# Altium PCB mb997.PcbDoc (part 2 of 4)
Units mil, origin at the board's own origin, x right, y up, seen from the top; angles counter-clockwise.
Board outline 2598.43 x 3818.9 mil, 2 copper layers (Top, Bottom), stack 62.402 mil thick; 205 components, 190 nets, 761 pads, 492 vias.
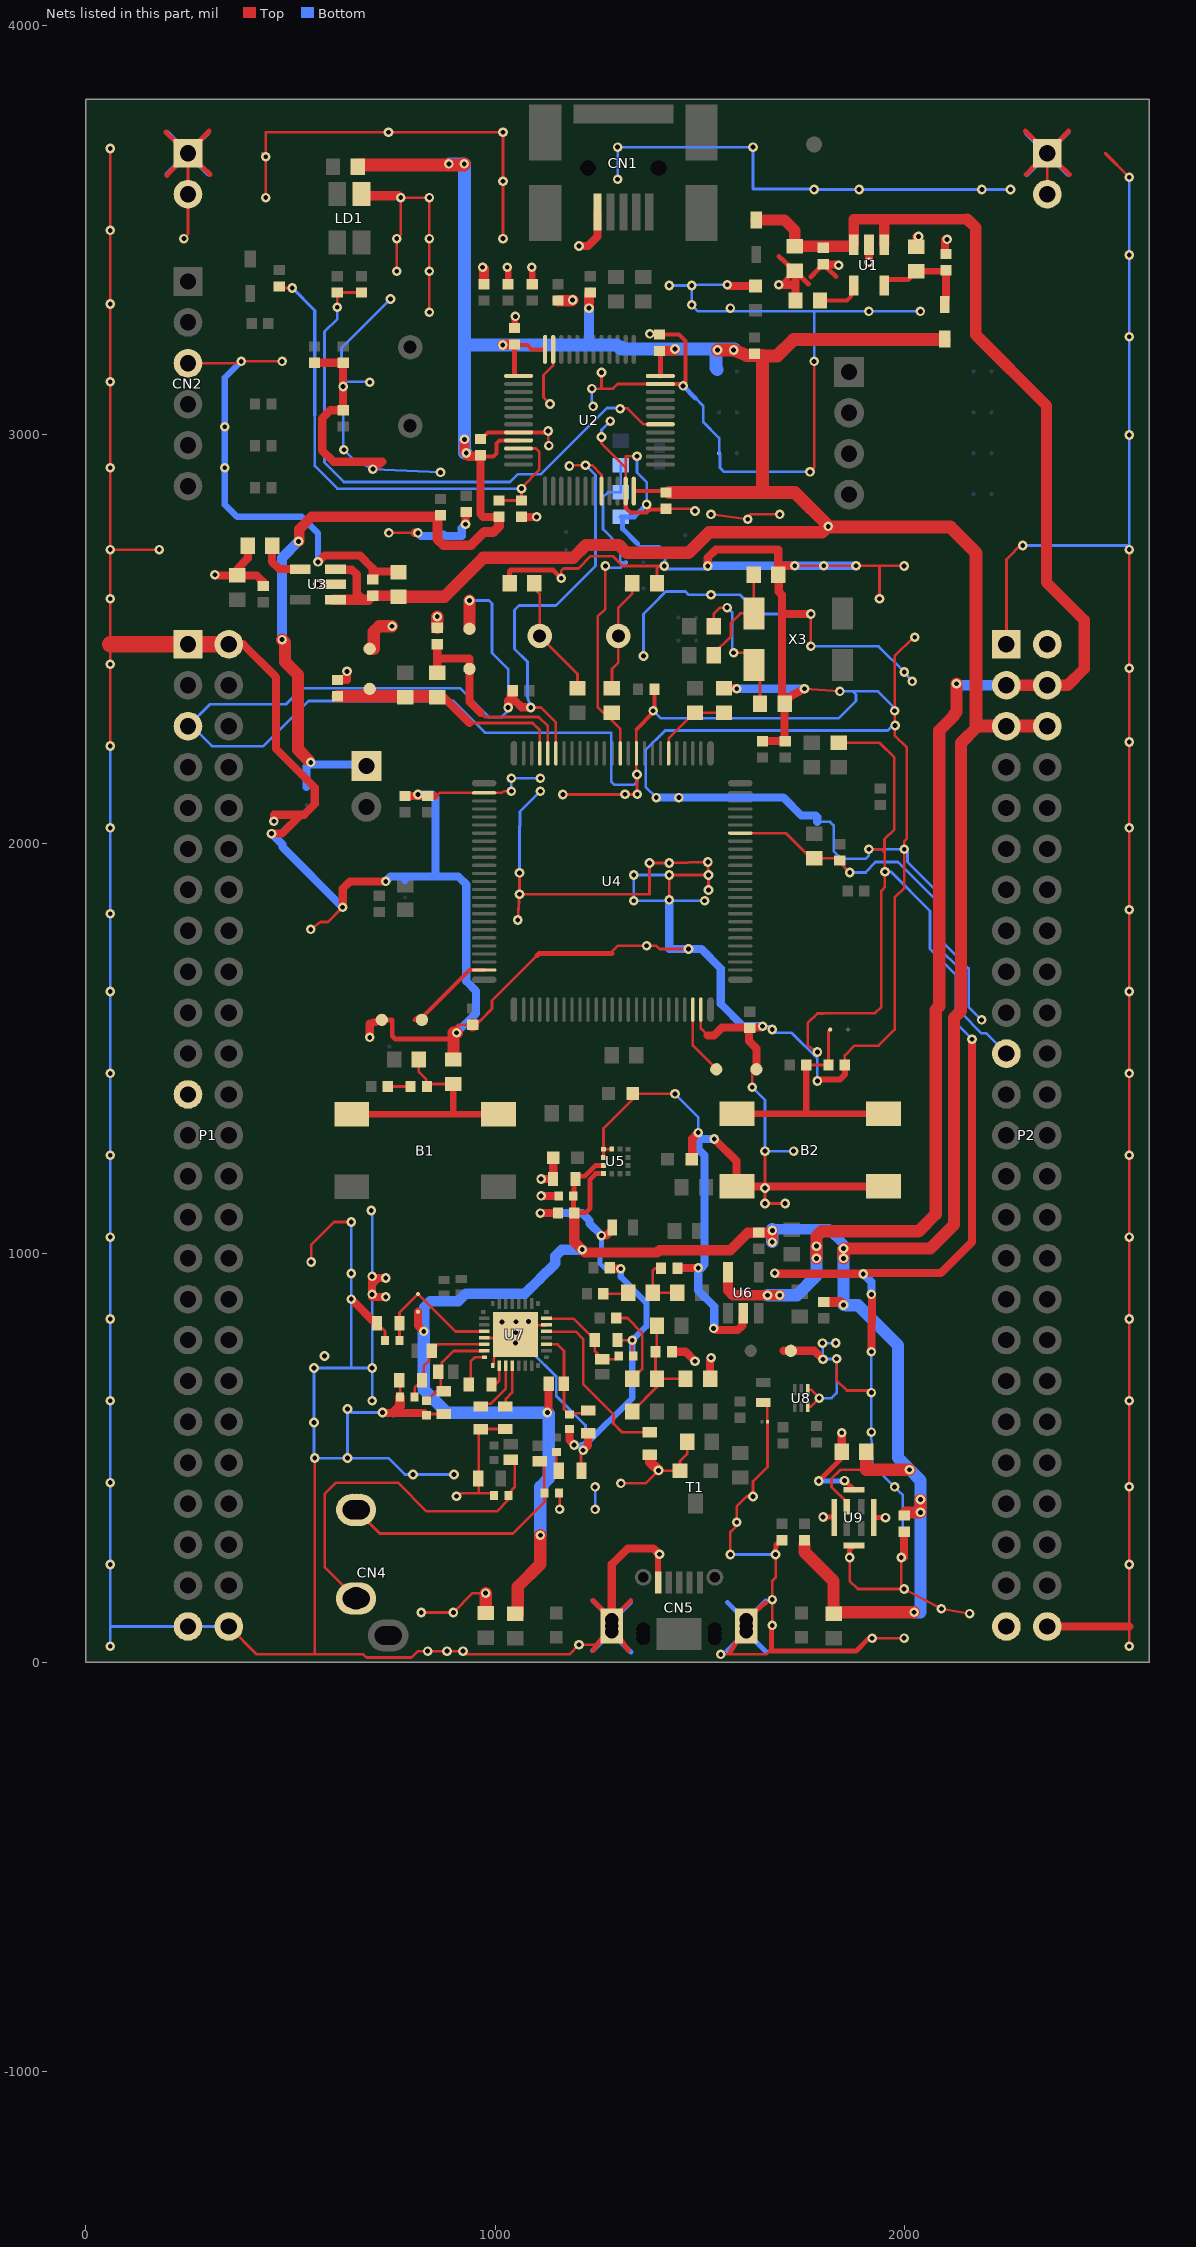
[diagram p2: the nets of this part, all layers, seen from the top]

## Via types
v1: diameter 23.62, hole 11.81, Top to Bottom, 485 vias
v2: diameter 19.68, hole 11.81, Top to Bottom, 7 vias

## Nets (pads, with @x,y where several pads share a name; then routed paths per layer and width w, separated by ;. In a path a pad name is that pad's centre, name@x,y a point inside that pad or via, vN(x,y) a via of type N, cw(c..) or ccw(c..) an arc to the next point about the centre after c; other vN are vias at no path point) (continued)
3V: C7.2 C8.2 C10.2 C12.1 C19.2 C20.2 C39.2 C58.2 C60.2 C65.2 C66.2 D3.2 JP1.1 L5.1 P2.5 P2.6 R1.2 R9.2 R14.2 R18.2 R19.1 R45.1 R51.1 R64.2 R66.2 R67.2 SB2.2 SB17.1 SB22.1 U2.1 U2.9 U2.24 U2.36 U2.48 U3.1 U3.3 U5.9 U5.10 U9.1 | length 14256.8
  Top w6.5: R1.2@663.82,3654.37 R1.2@663.82,3658.9 ; R18.2@858.9,2798.9 R18.2@859.08,2799.07 ; U2.1@1047.24,3147.3 1047.24,3144.93 1048.91,3143.27 U2.1@1057.11,3143.27 ; R14.2@1633.82,3197.36 1633.82,3196.98 1629.75,3192.91 R14.2@1637.62,3192.91 ; R64.2@1755.67,288.18 R64.2@1755.67,298.39 ; U9.1@1859,379.91 1859,391.42 1821.87,428.55 1821.87,448.54 1843.73,470.4 1906.71,470.4 ; C60.2@1999.21,358.9 2006.46,366.14 C60.2@2007.51,367.2
  Top w9.84: C10.2@963.81,2946.79 995.9,2946.79 1002.81,2953.7 1002.81,2977.99 1010.61,2985.79 U2.9@1057.11,2985.79 ; C7.2@1047.24,3220.16 1048.5,3218.9 1078.54,3218.9 1089.21,3208.23 U2.48@1122.07,3208.23 ; U2.24@1338.61,2861.77 1414.13,2861.77 C12.1@1417.32,2858.58
  Top w11.81: U2.1@1047.24,3147.3 C7.2@1047.24,3220.16 ; C66.2@1195.91,1170.16 C66.2@1195.91,1180.99 ; U5.10@1264.37,1194.05 1245.44,1194.05 1231.79,1180.4 1231.79,1109.43 1221.15,1098.8 1193.29,1098.8 C39.2@1193.29,1097.52 1190.91,1099.9 C65.2@1190.91,1139.61 1192.2,1140.89 1192.2,1169.37 1192.99,1170.16 1201.81,1170.16 1201.81,1180.99 1201.81,1186.86 1202.6,1187.65 1219.3,1187.65 1245.71,1214.06 U5.9@1264.68,1214.06 ; C8.2@1403.26,3204.41 1403.57,3204.1 U2.36@1403.57,3143.26
  Top w20: U3.3@610.24,2671.26 612.05,2669.45 650.03,2669.45 661.74,2657.73 661.74,2611.88 677.17,2596.46 ; SB22.1@811.27,856.45 811.27,822.62 v1(825.28,808.61) ; C10.2@963.81,2949.3 963.81,2946.79 963.81,2805.5 970.41,2798.9 R19.1@1002.81,2798.9 ; v1(1127.55,610.24) 1127.55,611.22 1130.51,614.18 L5.1@1130.51,680.03
  Top w23.62: R18.2@858.9,2798.9 858.9,2744.09 873.1,2729.9 940.76,2729.9 972.83,2761.97 995.59,2761.97 1009.21,2775.59 R19.1@1009.21,2798.9 R19.1@1002.81,2798.9 ; R18.2@859.08,2799.07 R18.2@866.14,2802.83 ; v1(924.81,2988.19) 924.81,2956.54 934.57,2946.79 949.21,2946.79 ; C10.2@963.81,2946.79 949.21,2946.79 ; C10.2@963.81,2949.3 949.21,2946.79 ; v1(1229.21,3308.9) 1229.21,3343.94 R9.2@1232.24,3346.97 ; C8.2@1401.57,3204.41 1403.26,3204.41 1439.21,3204.41 v1(1439.21,3208.9) ; C12.1@1417.32,2858.58 C12.1@1425.2,2858.58
  Top w25: v1(519.21,2738.9) 521.18,2738.9 521.18,2768.9 551.18,2798.9 R18.2@858.9,2798.9 ; U3.1@604.33,2595.77 605.02,2596.46 U3.1@610.24,2596.46 677.17,2596.46 689.98,2596.46 699.51,2605.98 C19.2@700.79,2605.98 761.65,2605.98 C20.2@763.78,2603.86 ; v1(1018.41,3218.9) 1018.41,3220.16 C7.2@1047.24,3220.16 ; C39.2@1193.29,1096.33 1193.29,1027.54 1219.84,1000.99 1395.31,1000.99 1401.21,1006.9 1574.27,1006.9 1616.8,1049.42 1676.97,1049.42 v1@1676.97,1035.82 ; v1(1676.97,1026.69) v1@1676.97,1035.82 ; v1(1677.21,1054.9) 1677.21,1035.82 v1@1676.97,1035.82 ; R51.1@1803.23,880.62 1811.36,880.62 1811.84,880.14 1843.97,880.14 v1(1851.21,872.9)
  Top w28: D3.2@2094.21,3232.28 2098.39,3232.28 D3.2@2098.39,3233.11
  Top w30: v1(479.21,2498.9) 486.21,2491.9 486.21,2444.9 518.02,2413.09 518.02,2230.03 v1@543.08,2204.97 ; C20.2@763.78,2603.86 875.95,2603.86 970.99,2698.9 1190.81,2698.9 1221.81,2729.9 1302.21,2729.9 1321.24,2710.87 1472.35,2710.87 1522.45,2760.97 1799.21,2760.97 v1(1813.82,2775.58) ; R66.2@1049.21,118.9 1055.12,118.9 1055.12,184.6 1110.33,239.81 v1(1110.33,310.52) ; R64.2@1755.67,288.18 1755.67,269.66 1826.77,198.56 1826.77,119.76 R67.2@1827.64,118.9 1830.79,122.05 v1(2023.62,122.05) ; v1(1851.21,986.9) v1(1851.21,1010.9) 2063.21,1010.9 2121.21,1068.9 2121.21,1574.9 2138.19,1591.88 2138.19,2246.42 2179.17,2287.4 ; C58.2@1906.71,514.12 1906.71,470.4 v1(2012.47,470.4) ; C60.2@2002.65,366.14 2006.46,366.14 v1(2039.37,366.14) v1(2039.37,397.64) ; 2175.21,2287.4 2179.17,2287.4 ; 2194.88,2287.4 2179.17,2287.4
  Top w31.5: R1.2@663.82,3658.9 924.21,3658.9 v1(924.21,3661.4) ; C12.1@1425.2,2858.58 1653.54,2858.58 ; v1(1543.18,3206.68) v1(1582.53,3206.68) 1614.17,3192.91 R14.2@1629.75,3192.91 ; R14.2@1637.62,3192.91 1653.54,3192.91 1653.54,3192.28 ; D3.2@2094.21,3232.28 1729.21,3232.28 1689.21,3192.28 1653.54,3192.28 ; 2175.21,2287.4 2175.21,2710.87 2112.25,2773.83 1816.82,2773.83 1732.06,2858.58 1653.54,2858.58 ; 2194.88,2287.4 P2.5@2249.21,2287.4 P2.6@2349.21,2287.4 ; 1653.54,2858.58 1653.54,3192.28
  Bottom w6.5: 1542.65,3158.92 SB2.2@1547.2,3154.37 ; v1(1851.21,872.9) 1856.53,872.9 v1@1857.21,872.22
  Bottom w19.68: SB17.1@539.21,2138.58 539.21,2188.9 v1@546.88,2196.56 ; v1(549.21,2198.9) v1@546.88,2196.56 ; JP1.1@693.22,2194.23 549.21,2194.23 v1@546.88,2196.56
  Bottom w23.62: 1229.21,3218.9 v1(1229.21,3308.9) ; 1314.81,3208.9 v1(1439.21,3208.9)
  Bottom w25: v1(479.21,2498.9) 479.21,2698.9 v1(519.21,2738.9) ; v1(825.28,808.61) 826.77,810.1 826.77,867.51 841.42,882.15 909.94,882.15 928.31,900.53 1061.92,900.53 1072.15,900.53 1079.44,907.7 1104.36,932.21 1108.56,936.1 1109.23,936.75 1146.6,974.11 1146.6,992.44 1162.39,1008.24 v1(1212.59,1008.24) ; v1@1676.97,1058.17 v1@1677.21,1058.17 ; v1(1851.21,1010.9) 1851.21,1022.17 1815.21,1058.17 v1@1680.48,1058.17 ; v1@1677.21,1058.17 v1@1680.48,1058.17 ; v1@1677.21,1058.17 v1(1677.21,1054.9) v1@1680.48,1058.17
  Bottom w30: v1(825.28,808.61) 825.28,666.4 882.1,609.58 1126.89,609.58 v1(1127.55,610.24) 1130.51,607.28 1130.51,448.75 1110.33,428.57 v1(1110.33,310.52) ; v1(1676.97,1026.69) v1@1676.97,1058.17 ; v1(1851.21,872.9) v1(1851.21,986.9) v1(1851.21,1010.9) ; v1@1857.21,872.22 1886.53,872.22 1984.09,774.66 1984.09,499.59 2012.87,470.8 2039.37,444.31 v1(2039.37,397.64) v1(2039.37,366.14) 2039.37,122.05 v1(2023.62,122.05)
  Bottom w31.5: v1(886.71,3661.4) v1(924.21,3661.4) 924.81,3661.4 924.81,3218.9 ; v1(929.32,2954.84) 924.81,2954.84 v1(924.81,2988.19) 924.81,3218.9 ; 1314.81,3208.9 1314.58,3208.66 ; 1542.65,3158.92 1539.21,3162.36 v1@1539.21,3208.66 ; v1(1543.18,3206.68) v1@1541.2,3208.66 ; 924.81,3218.9 v1(1018.41,3218.9) 1229.21,3218.9 1297.01,3218.9 1302.01,3213.9 ; 1302.01,3213.9 1307.38,3213.9 1312.38,3208.9 1312.61,3208.66 ; 1302.01,3213.9 1307.01,3208.9 1307.25,3208.66 1312.61,3208.66 ; 1312.61,3208.66 1314.58,3208.66 ; 1314.58,3208.66 v1@1539.21,3208.66 ; v1@1539.21,3208.66 v1@1541.2,3208.66 ; v1@1541.2,3208.66 v1@1582.53,3208.66 ; v1@1582.53,3208.66 1584.52,3208.66 v1(1582.53,3206.68) v1@1582.53,3208.66
5V: C1.2 C2.2 D1.2 P2.3 P2.4 U1.1 U1.3 U6.5 | length 4304.4
  Top w6.5: C2.2@1801.71,3456.4 C2.2@1801.71,3459.96 ; 2153.21,3525.9 2153.6,3526.28
  Top w25: U6.5@1568.74,942.9 1568.74,908.9 1580.74,896.9 v1(1665.21,896.9) v1(1695.21,896.9) ; U1.3@1869.21,3459.96 1871.69,3459.96 U1.3@1875.95,3464.21 1875.95,3525.9 1950.75,3525.9 ; U1.1@1950.75,3464.21 1950.75,3525.9 ; 2153.21,3525.9 1950.75,3525.9
  Top w27.56: D1.2@1637.76,3524.45 1706.69,3524.45 1732.24,3498.9 C1.2@1732.24,3459.96 1801.71,3459.96 U1.3@1869.21,3459.96 ; 2153.6,3526.28 2174.21,3505.66 2174.21,3243.77 2347.08,3070.9 2347.08,2638.9 2439.21,2546.77 2439.21,2427.55 2399.07,2387.4 P2.4@2349.21,2387.4 P2.3@2249.21,2387.4
  Top w30: v1(1785.21,986.9) v1(1785.21,1016.9) 1785.21,1040.9 1797.21,1052.9 2034.21,1052.9 2076.21,1094.9 2076.21,1593.9 2085.21,1602.9 2085.21,2276.9 2121.21,2312.9 2121.21,2316.34 2127.21,2322.34 v1(2127.21,2390.9)
  Bottom w25: v1@2127.21,2389.15 v1(2127.21,2390.9) 2133.21,2387.4 P2.3@2249.21,2387.4
  Bottom w30: v1(1665.21,896.9) v1(1695.21,896.9) 1737.21,896.9 1785.21,944.9 v1(1785.21,986.9) v1(1785.21,1016.9)
AIN_1: R2.2 R19.2 R20.2 U2.10 | length 1270.9
  Top w6.5: R19.2@1009.21,2838.9 R20.2@1064.09,2838.9 v1(1064.09,2867.9) 1064.09,2869.97 1107.21,2913.09 1107.21,2958.19 1099.3,2966.1 U2.10@1057.11,2966.1
  Top w7.87: R2.2@472.44,3361.89 476.06,3358.27 v1(503.94,3358.27) ; R20.2@1064.09,2838.9 R20.2@1070.87,2838.9
  Bottom w6.5: 559.06,3047.3 559.06,2923.36 614.51,2867.9 v1(1064.09,2867.9)
  Bottom w7.87: v1(503.94,3358.27) 559.06,3303.15 559.06,3047.3
AVDD: C42.2 C48.2 L2.2 U7.23 | length 238.2
  Top w6.5: U7.23@1125,839.75 1191.32,839.75 C42.2@1243.49,787.58 1243.49,759.96 1261.43,742.02 L2.2@1261.43,740.63 1294.7,740.63 C48.2@1302.09,748.01
BOOT0: P2.21 R30.2 R31.1 U4.94 | length 1029.1
  Top w6.5: U4.94@1598.96,2026.06 1709.93,2026.06 1771.29,1964.7 R30.2@1779.28,1964.7 1841.75,1964.7 1841.75,1958.89 R31.1@1842.24,1958.96 1842.24,1955.35 1840.76,1955.35 v1(1866.21,1929.9)
  Bottom w6.5: v1(1866.21,1929.9) 1905.2,1929.9 1928.81,1955.35 1983.9,1955.35 2078.34,1860.91 2078.34,1750.73 2141.3,1687.77 2141.3,1583.65 2187.62,1537.33 2199.28,1537.33 P2.21@2249.21,1487.4
CPVDD: C41.2 C45.2 L4.2 U7.7 | length 243.2
  Top w6.5: C41.2@832.56,639.03 855.39,661.85 C45.2@874.23,661.85 867,669.08 L4.2@867,709.33 ; L4.2@860.48,710.17 869.6,719.3 869.6,732.35 897.93,760.68 973.1,760.68 U7.7@973.42,761.01
DBVDD: C46.2 C50.2 SB22.2 U7.4 | length 334.9
  Top w6.5: C50.2@765.85,785.5 C50.2@766.05,785.7 C50.2@766.14,785.79 ; C50.2@767.37,787.01 C50.2@766.14,785.79 ; U7.4@973.42,808.26 902.77,808.26 SB22.2@811.27,899.76 766.14,854.63 C46.2@766.14,828.78 C50.2@766.14,785.79
DCVDD: C40.2 C43.2 L3.2 U7.6 | length 265.9
  Top w6.5: C40.2@802.99,647.58 802.99,671.3 825.28,693.59 825.28,724.06 838.88,737.66 838.88,755.07 860.57,776.76 U7.6@973.42,776.76
GND: B2.1 B2.2 C1.1 C2.1 C3.2 C4.1 C5.1 C6.1 C7.1 C8.1 C9.1 C10.1 C11.1 C12.2 C13.1 C14.1 C15.1 C16.2 C17.2 C18.1 C19.1 C20.1 C21.1 C22.2 C23.2 C24.2 C25.1 C26.1 C27.2 C28.2 C29.1 C30.1 C31.1 C32.1 C33.2 C34.1 C35.2 C36.2 C37.1 C39.1 C40.1 C41.1 C42.1 C43.1 C45.1 C46.1 C47.1 C48.1 C49.2 C50.1 C52.2 C53.1 C55.1 C56.1 C57.1 C58.1 C59.2 C60.1 C61.2 C62.2 C65.1 C66.1 CN1.5 CN2.3 CN5.0 CN5.5 JP2.1 JP2.2 JP3.1 JP3.2 LD1.1 LD2.2 LD3.2 LD4.2 LD5.2 LD6.2 P1.1 P1.2 P1.5 P1.23 P1.49 P1.50 P2.1 P2.2 P2.49 P2.50 R5.1 R6.1 R7.1 R8.2 R13.2 R20.1 R28.2 R39.1 R43.2 R44.2 R52.2 R57.1 R63.1 R65.2 R70.1 R71.1 SB6.2 SB10.1 SB18.1 SB19.1 T1.2 U1.2 U2.8 U2.20 U2.23 U2.35 U2.47 U3.2 U4.10 U4.20 U4.27 U4.74 U5.6 U5.7 U5.8 U6.2 U7.5 U7.9 U7.22 U7.33 U8.3 U8.4 U9.5 U10.2 U11.2 | length 54676.6
  Top w6.5: v1(59.21,2238.9) v1(59.21,2438.9) 59.21,2487.4 v1(59.21,2598.9) v1(59.21,2718.9) ; v1(59.21,3698.9) v1(59.21,3498.9) v1(59.21,3318.9) v1(59.21,3128.9) v1(59.21,2918.9) v1(59.21,2718.9) ; v1(179.21,2718.9) v1(59.21,2718.9) ; v1(239.21,3478.9) 249.21,3488.9 JP2.2@249.21,3587.4 JP2.1@249.21,3687.4 ; CN2.3@249.21,3174.02 374.33,3174.02 v1(379.21,3178.9) v1(479.21,3178.9) ; P1.50@349.21,87.4 417.29,19.33 559.21,19.33 ; 430.71,3687.4 v1(439.21,3678.9) ; v1(439.21,3578.9) v1(439.21,3678.9) ; v1(549.21,1790.9) 573.21,1808.9 591.21,1808.9 v1(627.21,1844.9) ; v1(550.21,977.9) 550.21,1019.9 606.21,1075.9 v1(648.21,1075.9) ; v1(559.21,498.9) 559.21,19.33 ; C46.1@711.02,828.78 730.62,809.19 C50.1@730.62,785.7 ; v1(740.16,2759.84) v1@803.15,2759.84 ; v1(759.21,3398.9) v1(759.21,3478.9) 769.21,3488.9 v1(769.21,3578.9) v1(839.21,3578.9) v1(839.21,3478.9) v1(839.21,3398.9) v1(839.21,3298.9) ; C43.1@765.76,689.19 767.56,687.39 C40.1@767.56,647.58 ; v1(819.14,121.64) v1(897.84,121.64) 945.06,168.86 v1(976.54,168.86) ; C41.1@832.56,603.59 835.7,606.73 C45.1@874.23,606.73 ; C32.1@834.88,2117.01 839.14,2112.75 846.76,2112.75 850.82,2116.81 856.28,2116.81 863.95,2124.48 1015.75,2124.48 1021.97,2128.78 1039.21,2128.78 v1(1039.5,2128.49) ; v1@897.84,1538.24 897.84,1546.22 909.21,1557.59 C34.1@945.06,1557.59 ; v1(905.51,405.51) 910.15,405.51 917.79,413.16 959.77,413.16 ; C34.1@944.36,1556.37 952.71,1556.37 965.24,1568.9 965.24,1569.83 992.28,1596.87 992.28,1616.94 1102.46,1727.12 ; C55.1@959.5,569.63 959.5,571.36 964.89,576.76 971.76,569.89 C56.1@1024.25,569.89 ; C10.1@963.81,2989.3 966.06,2989.3 C10.1@970.65,2993.88 ; C55.1@964.69,569.63 959.77,569.63 959.77,413.16 ; U7.5@973.42,792.51 1009.54,792.51 1022.48,805.44 v1(1050.03,805.44) ; U7.9@994.09,724.56 994.09,728.89 996.26,731.06 996.26,741.38 997.34,742.47 997.34,750.55 1005.69,758.9 1028.15,758.9 v1(1049.21,779.96) ; C59.2@996.77,413.16 959.77,413.16 ; v1(1019.21,3478.9) v1(1019.21,3618.9) v1(1019.21,3738.9) v1(739.21,3738.9) 439.21,3738.9 v1(439.21,3678.9) ; v1(1050.87,831.89) 1075.9,831.89 1084.24,823.56 U7.22@1115.26,823.56 ; v1(1055.24,1813.69) v1(1059.21,1876.65) ; v1(1059.21,1928.9) v1(1059.21,1876.65) ; v1(1086.72,2333.11) 1111.77,2333.11 1148.17,2296.71 U4.20@1148.17,2220.94 ; U7.22@1115.26,822.92 1123.92,822.92 1125,824 U7.22@1115.26,824 ; v1(1129.21,3008.9) 1129.21,2974.9 v1(1131.21,2972.9) ; v1(1133.86,3074.8) 1118.13,3090.53 1118.13,3145.67 1141.76,3169.29 U2.47@1141.76,3208.23 ; C66.1@1141.23,1180.99 C66.1@1141.89,1181.65 ; LD4.2@1141.23,1232.24 LD4.2@1141.89,1232.9 ; C62.2@1155.71,414.14 1157.48,412.37 v1(1157.48,374.02) ; v1(1161.21,2648.9) 1161.21,2666.9 1167.21,2672.9 1203.21,2672.9 1233.21,2702.9 1287.21,2702.9 1311.21,2678.9 1401.21,2678.9 ; v1(1165.42,2120.62) v1@1317.21,2120.62 ; v1(1181.16,2923.36) 1183,2925.2 v1(1220.47,2925.2) 1236.24,2925.2 1259.87,2901.57 U2.20@1259.87,2861.77 ; v1(1192.86,530.88) v1@1192.86,531.55 ; R71.1@1205.65,480.21 1209.73,484.29 1209.73,508.16 1214.87,513.3 v1(1214.87,517.93) ; R71.1@1210.71,467.86 R71.1@1213.31,469.77 ; C47.1@1227.68,551.43 1227.68,557.24 C47.1@1227.68,559.84 ; v1(1236.25,3112.24) 1259.86,3112.24 ; v1(1259.86,2994.19) 1259.86,2978.45 1318.92,2919.39 ; v1(1259.86,3151.59) 1259.86,3112.24 ; U5.8@1264.68,1233.74 U5.7@1264.68,1253.43 ; CN5.0@1284.84,74.62 1253.16,42.94 1249.31,42.94 v1(1204.77,42.94) 1181.16,19.33 929.32,19.33 v1(921.45,27.2) v1(882.1,27.2) v1(834.88,27.2) 811.27,27.2 795.53,11.46 685.35,11.46 677.48,19.33 559.21,19.33 ; U5.6@1284.86,1253.92 1265.18,1253.92 U5.7@1264.68,1253.43 ; 1285.2,1731.91 1285.2,1736.71 1299.21,1750.73 v1(1370.04,1750.73) 1393.65,1750.73 1401.52,1742.86 v1(1472.35,1742.86) ; C42.1@1298.61,787.58 1299.46,786.72 v1(1334.99,786.72) 1334.99,750.55 C48.1@1337.53,748.01 ; v1@1307.09,438.29 v1(1307.09,437.01) 1367.32,437.01 v1(1399.21,468.9) 1400.21,467.9 T1.2@1451.71,467.9 1451.71,491.4 1469.21,508.9 R57.1@1469.21,538.9 ; v1(1317.21,2120.9) v1@1317.21,2120.62 ; U2.23@1318.92,2861.77 1318.92,2919.39 ; 1345.02,2279.53 1345.02,2168.14 1345.16,2168 v1@1346.46,2166.7 ; v1(1346.46,2169.29) v1@1346.46,2166.7 ; v1(1346.43,2946.97) 1318.92,2946.97 1318.92,2919.39 ; v1(1347.21,2120.9) v1@1346.46,2120.62 ; LD3.2@1348.74,1388.9 1290.01,1330.16 1264.68,1304.84 U5.7@1264.68,1253.43 ; LD3.2@1349.21,1388.9 v1(1439.21,1388.9) ; C15.1@1395.21,2636.9 1395.21,2672.9 1401.21,2678.9 ; U2.35@1403.57,3123.58 1299.21,3123.58 1287.87,3112.24 1259.86,3112.24 ; v1(1413.21,2678.9) 1401.21,2678.9 ; C12.2@1417.32,2818.58 1478.92,2818.58 1483.39,2814.11 v1(1488.09,2813.18) ; v1(1425.21,1862.9) 1425.13,1862.98 v1(1425.13,1923.87) v1(1521.21,1923.87) ; U4.74@1502.5,1594.96 1502.5,1548.57 1519.57,1531.5 ; v1(1521.21,1886.9) v1(1521.21,1923.87) ; v1(1527.21,2804.9) v1(1617.21,2792.9) 1623.03,2792.9 1623.03,2804.9 v1(1695.21,2804.9) ; v1(1551.05,19.33) 1662.92,19.33 1672.62,29.04 ; v1(1574.66,263.3) 1574.66,318.39 1590.4,334.13 v1(1590.4,342) 1590.4,381.35 1614.01,404.96 v1(1629.75,404.96) 1629.75,442.18 1665.21,477.64 U11.2@1665.21,584.97 ; v1(1628.21,1404.9) 1628.21,1443.9 C36.2@1638.21,1453.9 ; U10.2@1654.68,634.29 1665.13,623.84 U11.2@1665.13,587.4 ; v1(1659.21,1248.9) 1659.21,1162.71 v1(1659.21,1158.9) v1(1659.21,1121.13) v1(1708.45,1121.13) ; v1(1676.97,90.16) v1(1676.97,153.12) 1676.97,198.9 1685.29,207.21 v1@1685.29,272.1 ; v1(1732.06,2679.39) v1(1802.89,2679.39) v1(1881.59,2679.39) 1939.21,2679.39 ; v1(1755.67,2378.9) v1(1842.24,2372.46) ; U8.3@1763.52,624.84 1771.31,624.84 v1(1791.98,645.51) 1771.31,666.18 U8.4@1763.52,666.18 ; U8.4@1763.52,674.08 U8.4@1764.2,673.39 ; v1(1769.21,2908.9) 1779.21,2918.9 v1(1779.21,3178.9) ; v1(1771.41,2482.64) v1(1771.41,2561.34) ; v1(1787.15,1491.02) 1763.54,1506.76 1763.54,1561.85 1787.15,1585.46 1802.89,1585.46 1803.48,1586.04 1928.23,1586.04 1943.39,1601.2 1943.39,1885.1 1951.84,1893.55 v1@1951.84,1939.02 ; U9.5@1826.97,354.85 U9.5@1828.48,353.34 ; v1(1834.37,741.73) 1834.37,688.9 1859.21,664.06 1919.21,664.06 v1(1919.21,658.9) ; R28.2@1839.21,2246.9 1939.33,2246.9 1975.33,2210.9 1975.33,2035.14 1951.33,2011.14 1951.33,1978.88 ; C58.1@1846.71,499.1 C58.1@1846.71,514.12 ; v1(1853.55,443.85) v1@1854.11,443.85 ; C37.1@1854.37,1459.54 1854.37,1483.15 1877.98,1506.76 1936.68,1506.76 1976.03,1546.11 1976.03,1868.78 1999.64,1892.39 v1(1999.64,1986.83) 1999.64,2006.51 2006.03,2012.9 2006.03,2234.9 1976.03,2264.9 v1(1976.03,2325.24) 1976.03,2459.03 2023.25,2504.9 v1(2025.21,2504.9) ; v1(1866.14,255.91) 1866.14,198.9 1886.14,178.9 v1(1999.21,178.9) ; v1(1913.07,1986.83) 1943.39,1986.83 1951.33,1978.88 ; v1(1920.94,58.68) 1998.99,58.68 v1(1999.21,58.9) ; v1(1939.21,2598.9) 1939.21,2679.39 ; v1(1952.42,1931.74) v1@1951.84,1939.02 ; v1(1992.13,255.91) 1992.13,185.98 v1(1999.21,178.9) ; v1(1999.21,2678.9) 1998.72,2679.39 1939.21,2679.39 ; v1(2159.21,118.9) v1(2090.21,130.9) v1(1999.21,178.9) ; P2.1@2249.21,2487.4 2249.21,2695.13 2288.56,2734.48 2289.21,2733.83 v1(2289.21,2728.9) ; JP3.2@2349.21,3587.4 JP3.1@2349.21,3687.4 ; 2490.71,3687.4 v1(2549.21,3628.9) ; v1(2549.21,38.9) 2549.21,87.4 v1(2549.21,238.9) v1(2549.21,428.9) v1(2549.21,638.9) v1(2549.21,838.9) v1(2549.21,1038.9) v1(2549.21,1238.9) v1(2549.21,1438.9) v1(2549.21,1638.9) v1(2549.21,1838.9) v1(2549.21,2038.9) v1(2549.21,2248.9) v1(2549.21,2428.9) v1(2549.21,2718.9) ; v1(1059.21,1876.65) 1377.21,1876.65 v1(1377.21,1952.9) v1(1425.13,1952.9) v1(1519.57,1955.35) v1(1521.21,1923.87) ; v1@1317.21,2120.62 v1@1346.46,2120.62 ; v1@1346.46,2120.62 v1@1346.46,2166.7 ; 1951.33,1978.88 1951.84,1978.37 v1@1951.84,1939.02
  Top w9.84: C10.1@970.65,2993.88 982.24,3005.47 1125.79,3005.47 v1(1129.21,3008.9) ; C8.1@1401.57,3244.41 1449.21,3244.41 1464.72,3228.9 1464.72,3128.9 v1@1459.21,3123.39 ; U2.35@1403.57,3123.58 1403.76,3123.39 v1@1459.21,3123.39 ; v1(1459.21,3118.9) v1@1459.21,3123.39
  Top w10: U2.23@1318.92,2861.77 1318.92,2821.05 1330.69,2809.28 1370.04,2809.28 1377.91,2817.15 1415.89,2817.15 C12.2@1417.32,2818.58 ; 1345.02,2279.53 1385.78,2320.29 v1(1385.78,2325.24) 1389.21,2323.72 C24.2@1389.21,2374.02
  Top w12: C33.2@722.92,1569.72 748.31,1569.72 748.31,1530.37 756.18,1522.5 889.97,1522.5 897.84,1530.37 v1(905.71,1538.24) ; C14.1@1035.21,2636.9 1035.21,2666.9 1037.62,2669.31 1140.8,2669.31 v1(1161.21,2648.9) ; 1102.46,1727.12 1107.26,1731.91 1285.2,1731.91 ; 1672.62,29.04 1675,27.2 ; v1(1676.97,90.16) 1675,88.19 1675,27.2 ; v1(1684.84,263.3) 1685.29,272.1 1686.03,286.85 1686.03,287.42 1699.77,301.16 R63.1@1700.58,298.39 ; v1(1790.55,442.94) C58.1@1846.71,499.1 ; v1(1801.37,354.85) U9.5@1826.97,354.85 ; v1@1854.11,443.85 U9.5@1876.71,421.25 ; v1(1866.14,255.91) 1866.14,274.85 U9.5@1876.71,285.43 ; v1(1920.94,58.68) 1913.07,58.68 1881.59,27.2 1675,27.2 ; U9.5@1924.94,353.34 v1(1953.66,353.34)
  Top w12.01: 195.32,3739 JP2.1@249.21,3687.4 ; 197.61,3633.51 JP2.1@249.21,3687.4 ; 300.81,3741.29 JP2.1@249.21,3687.4 ; 303.1,3635.8 JP2.1@249.21,3687.4 ; 1238.39,28.9 1249.31,42.94 1278.07,79.89 CN5.0@1284.84,88.6 1291.32,78.98 1325,29 ; 1238.39,150.79 CN5.0@1284.84,103.76 1331.29,150.52 ; 1574.64,26.4 1607.29,78.55 CN5.0@1613.58,88.6 ; CN5.0@1613.58,103.76 1660.03,145.2 ; 1693.35,3435.66 C1.1@1732.24,3399.96 1720.07,3387.46 v1@1701.67,3368.57 ; C1.1@1733.74,3398.46 1746.24,3386.29 1765.13,3367.89 ; 1771.13,3385.01 1789.54,3403.9 C2.1@1801.71,3416.4 1814.21,3404.22 1833.1,3385.82 ; 2295.11,3741.6 2349,3690 2347.8,3688.75 2297.4,3636.11 ; 2400.81,3741.29 JP3.1@2349.21,3687.4 2403.1,3635.8
  Top w15: CN5.5@1398.03,194.9 1398.03,260.24 v1(1401.57,263.78) ; v1(1787.15,1420.19) 1790.76,1423.8 1842.24,1423.8 1854.37,1435.93 C37.1@1854.37,1459.54
  Top w15.75: v1(1029.21,3408.9) 1031.46,3406.65 R6.1@1031.46,3367.28 ; C7.1@1047.24,3260.16 1047.24,3286.93 v1(1049.21,3288.9) ; v1(1089.21,3408.9) 1090.51,3407.6 R7.1@1090.51,3367.28 ; v1(1377.91,3246.03) 1393.65,3244.41 C8.1@1401.57,3244.41
  Top w19.68: R20.1@1064.09,2798.9 v1(1101.21,2798.9) ; v1(1535.31,1278.53) 1589.21,1224.63 1589.21,1164.03 B2.2@1590.53,1162.71 1659.21,1162.71 B2.1@1948.8,1162.71 ; v1(1919.21,758.9) 1920.94,897.17 v1(1919.21,898.9)
  Top w20: v1(314.96,2657.48) 316.46,2655.98 C17.2@370.08,2655.98 ; P1.2@349.21,2487.4 384.35,2487.4 464.57,2407.18 464.57,2232.28 559.06,2137.8 559.06,2096.9 533.13,2070.98 525.21,2070.98 ; C13.1@395.2,2728.35 395.2,2696.85 370.08,2671.73 C17.2@370.08,2655.98 ; C18.1@433.07,2630.24 433.07,2640.24 417.32,2655.98 C17.2@370.08,2655.98 ; v1(453.21,2024.9) 479.13,2024.9 525.21,2070.98 ; v1(459.21,2054.9) 459.21,2070.98 525.21,2070.98 ; R13.2@558.21,3175.5 C6.1@628.41,3175.5 v1(628.41,3117.5) C9.1@628.41,3059.5 597.21,3059.5 577.21,3039.5 577.21,2961.5 605.01,2933.7 724.7,2933.7 v1(701.09,2915.49) ; v1(566.93,2633.86) U3.2@610.24,2633.86 U3.2@616.93,2633.86 ; v1(566.93,2688.98) 582.68,2704.72 669.29,2704.72 700.79,2673.23 700.79,2665.35 ; C25.1@614.52,2400.33 637.8,2400.33 v1(637.8,2421.26) ; v1(627.21,1844.9) 627.21,1890.13 645.21,1908.13 v1(732.57,1908.13) ; v1(648.21,887.4) C46.1@708.93,826.69 ; v1(693.21,1526.9) 693.21,1560.07 C33.2@722.92,1569.72 ; v1@699.21,892.9 v1(732.57,892.9) ; v1(699.21,898.9) 699.21,924.07 ; v1(699.21,942.9) 699.21,924.07 ; C19.1@700.79,2645.98 700.79,2665.35 ; v1(724.41,610.24) 725.1,609.54 729.74,609.54 730.07,609.21 C41.1@825.96,609.21 ; v1(732.57,938.9) 732.27,938.6 713.74,938.6 699.21,924.07 ; C20.1@763.78,2663.86 762.28,2665.35 700.79,2665.35 ; C31.1@779.79,2117.01 v1@811.27,2117.01 ; v1@803.15,2759.84 803.27,2759.72 811.14,2759.72 v1(811.02,2759.84) ; v1(811.27,2120.62) v1@811.27,2117.01 ; C41.1@827.38,607.8 831.58,603.59 C41.1@832.56,603.59 ; 850.82,2116.81 850.62,2117.01 C32.1@834.88,2117.01 v1@811.27,2117.01 ; v1(927.21,2780.9) 927.21,2790.94 C11.1@929.13,2810.71 ; v1(1031.63,2333.11) 1031.63,2349.61 1048.14,2349.61 ; C26.1@1042.99,2374.02 1037.29,2366.21 1037.29,2360.47 1048.14,2349.61 ; v1(1086.72,2333.11) 1085.96,2333.87 1063.88,2333.87 1048.14,2349.61 ; v1(1110.33,1097.52) C39.1@1153.29,1097.52 ; v1(1112.19,1139.61) C65.1@1155.48,1139.61 ; v1(1112.19,1180.99) C66.1@1141.23,1180.99 ; C66.1@1141.89,1181.65 LD4.2@1141.89,1232.9 ; C53.1@1181.16,569.69 1181.16,543.25 v1@1192.86,531.55 ; v1(1204.72,3460.63) 1226.61,3460.63 1250.23,3484.25 CN1.5@1250.23,3543.35 ; v1(1214.87,517.93) 1226.67,529.73 1226.67,557.24 C47.1@1227.68,557.24 ; v1(1259.37,1042.43) 1260.06,1043.12 1271.44,1043.12 LD6.2@1277.68,1049.37 ; R43.2@1279.86,963.73 1279.86,961.4 v1(1306.71,961.4) ; CN5.0@1284.84,88.6 CN5.0@1284.84,103.76 1284.84,239.3 1323.84,278.3 1387.06,278.3 v1(1401.57,263.78) ; C24.2@1389.21,2374.02 C24.2@1389.21,2377.9 ; R52.2@1431.71,758.9 1464.69,758.9 v1(1488.09,735.5) ; R44.2@1445.2,962.6 1445.2,963.73 v1(1495.96,963.73) ; LD5.2@1481.67,1224.75 1481.67,1279.97 v1(1495.96,1294.27) ; v1(1519.21,2678.9) 1519.21,2698.9 1539.21,2718.9 1691.42,2718.9 1691.42,2679.39 ; 1519.57,1531.5 1534.84,1531.5 1554.24,1550.9 C35.2@1620.21,1550.9 ; C52.2@1525.2,692.6 1525.2,741.73 v1(1527.56,744.09) ; v1(1533.71,815.81) 1534.69,815.81 1538.97,811.53 1592.62,811.53 1604.33,823.25 1604.33,828.69 1604.43,828.78 1604.43,841.18 U6.2@1606.14,842.9 ; C28.2@1559.06,2380.39 1588.72,2380.39 v1(1590.21,2378.9) ; v1(1566.93,3366.14) 1569.9,3363.17 LD2.2@1636.12,3363.17 ; C35.2@1621.88,1549.72 1622.15,1549.45 1622.07,1549.72 1622.05,1549.77 C35.2@1621.71,1550.9 ; C36.2@1638.21,1448.9 1638.21,1453.9 1638.21,1499.9 1620.21,1517.9 C35.2@1620.21,1550.9 ; v1@1650.21,1550.9 C35.2@1621.71,1550.9 ; v1@1650.25,1550.86 v1(1653.36,1553.98) ; C29.1@1653.36,2250.8 C30.1@1708.45,2250.8 1706.64,2263.17 1706.64,2327.25 1700.79,2333.11 C27.2@1700.79,2336.14 ; v1(1683.21,950.9) 1683.91,950.2 1686.47,950.2 1687.23,949.45 v1@1898.67,949.45 ; v1(1692.91,3366.14) 1733.74,3366.14 ; 1705.18,760.98 1780.46,760.98 v1(1801.01,740.43) ; v1(1732.06,2679.39) 1691.42,2679.39 ; C1.1@1732.24,3399.96 1733.74,3398.46 1733.74,3366.14 ; C5.1@1733.74,3327.6 1733.74,3366.14 ; v1(1755.67,2378.9) 1716.54,2358.27 1716.54,2351.89 C27.2@1707.17,2342.52 C27.2@1700.79,2336.14 ; v1(1771.41,2561.34) 1700.79,2561.34 ; C2.1@1801.71,3416.4 1816.31,3415.42 1837.69,3415.42 v1(1839.21,3413.9) ; C58.1@1846.87,514.12 v1(1846.87,560.9) ; v1(1899.21,948.9) 1899.21,950.9 2088.91,950.9 2164.91,1026.9 v1(2164.91,1522.5) ; U1.2@1913.35,3464.21 1913.35,3421.3 v1(1913.39,3421.26) ; v1(1992.13,255.91) 1999.21,255.91 C60.1@1999.21,318.9 ; C3.2@2029.21,3458.9 2029.21,3483.9 v1(2034.21,3483.9) ; C4.1@2101.71,3441.4 2101.6,3443.93 2099.21,3446.31 2099.21,3476.9 v1(2104.21,3476.9) ; P2.50@2349.21,87.4 2549.21,87.4 ; C35.2@1620.21,1550.9 C35.2@1621.71,1550.9 ; 1691.42,2679.39 C16.2@1691.42,2657.48 1692.71,2656.19 1692.71,2616.43 1700.79,2608.35 1700.79,2561.34 ; C27.2@1700.79,2336.14 1700.79,2561.34
  Top w23.62: LD1.1@673.19,3583.5 764.61,3583.5 v1(769.21,3578.9) ; v1(969.21,3408.9) 972.4,3405.71 R5.1@972.4,3367.28
  Top w25: 751.61,610.24 767.56,626.19 C40.1@767.56,647.58 ; C57.1@1377.95,506.91 1377.95,490.16 v1(1399.21,468.9)
  Top w27.56: R8.2@1153.5,3327.28 1187.6,3327.28 v1(1189.21,3328.9)
  Top w30: C22.2@693.22,2476.55 703.4,2476.55 703.4,2518.36 716.54,2531.5 v1(748.03,2531.5) ; C21.1@858.27,2527.87 v1(858.27,2555.12) ; R39.1@897.21,1472.9 897.21,1478.27 897.84,1478.9 897.84,1530.37 897.84,1538.24 v1(905.71,1538.24) ; C23.2@937.01,2525.38 v1(937.01,2594.49) ; C34.1@944.36,1556.37 C34.1@945.06,1557.59 ; R65.2@976.54,120.16 v1(976.54,168.86)
  Top w40: 59.21,2487.4 P1.1@249.21,2487.4 P1.2@349.21,2487.4
  Bottom w6.5: v1(59.21,38.9) 59.21,87.4 ; v1(59.21,2238.9) v1(59.21,2038.9) v1(59.21,1828.9) v1(59.21,1638.9) v1(59.21,1438.9) v1(59.21,1238.9) v1(59.21,1038.9) v1(59.21,838.9) v1(59.21,638.9) v1(59.21,438.9) v1(59.21,238.9) 59.21,87.4 ; P1.50@349.21,87.4 P1.49@249.21,87.4 59.21,87.4 ; v1(648.21,1075.9) v1(648.21,949.9) v1(648.21,887.4) 648.21,718.9 ; v1(693.22,3127.98) 692.3,3128.9 624.21,3128.9 ; v1(697.21,1103.9) 699.21,1101.9 v1(699.21,942.9) v1(699.21,898.9) ; v1(699.21,638.9) v1(699.21,718.9) ; v1(724.41,610.24) 647.87,610.24 v1(639.21,618.9) v1(639.21,498.9) ; v1(732.57,892.9) 705.21,892.9 v1(699.21,898.9) ; v1(744.21,3331.4) 624.21,3211.4 624.21,3128.9 ; v1(866.36,2907.62) v1(701.09,2915.49) 653.87,2939.1 v1(630.26,2962.71) 628.41,2964.56 v1(628.41,3117.5) 632.01,3121.1 624.21,3128.9 ; v1(899.21,458.9) v1(799.21,458.9) 779.21,458.9 739.21,498.9 v1(639.21,498.9) ; v1(937.01,2594.49) 984.25,2594.49 992.13,2586.61 992.13,2466.76 1031.5,2427.39 v1@1031.5,2340.98 ; v1(1031.63,2333.11) v1@1031.5,2340.98 ; v1(1039.5,2128.49) v1(1039.5,2159.97) v1(1110.33,2159.97) ; v1(1050.87,831.89) 1050.45,831.48 1050.45,805.86 v1(1050.03,805.44) 1049.62,805.03 1049.62,780.37 v1(1049.21,779.96) 1067.88,779.96 1087.99,759.85 1149.16,698.68 1149.16,650.34 1220.47,579.03 1220.47,541.73 1208.34,529.6 ; v1(1059.21,1928.9) 1059.21,2042.9 1060.74,2044.43 1060.74,2078.9 v1(1110.33,2128.49) ; v1(1086.72,2333.11) 1078.85,2358.27 1078.85,2444.84 1047.24,2476.45 1047.24,2570.87 1058.49,2582.12 1148.21,2582.12 1245.21,2679.12 1245.21,2901.16 1221.17,2925.2 v1(1220.47,2925.2) ; v1(1192.86,530.88) 1206.82,530.88 1208.34,529.37 ; v1(1236.25,3112.24) 1236.25,3071.86 v1(1239.21,3068.9) ; v1(1244.12,373.48) v1(1244.12,428.57) ; v1(1259.86,2994.19) 1259.86,3011.55 v1(1281.21,3032.9) ; v1(1299.21,3623.79) v1(1299.21,3702.49) v1(1629.75,3702.49) 1629.75,3600.18 1777.93,3600.18 v1(1779.21,3598.9) v1(1889.21,3598.9) v1(2189.21,3598.9) v1(2259.21,3598.9) ; v1(1346.46,2169.29) 1346.46,2152.1 1338.59,2144.23 1291.33,2144.23 1283.46,2152.1 1283.46,2271.65 975.04,2271.65 897.84,2348.85 543.69,2348.85 433.51,2238.67 307.59,2238.67 258.86,2287.4 P1.5@249.21,2287.4 302.79,2340.98 488.6,2340.98 527.95,2380.33 913.58,2380.33 984.41,2309.5 1015.89,2309.5 1031.5,2325.1 v1@1031.5,2340.98 ; v1(1346.43,2946.97) 1346.43,2907.23 1370.04,2883.62 v1(1370.04,2828.92) 1361.61,2820.48 ; 1347.61,2733.3 1354.3,2726.61 1401.52,2726.61 1417.26,2710.87 v1(1413.21,2678.9) 1419.21,2672.9 1419.21,2671.52 1511.83,2671.52 v1(1519.21,2678.9) v1@1519.57,2679.26 ; v1(1362.17,2459.03) 1362.17,2561.34 1401.52,2600.69 1401.52,2601.22 1416.73,2616.43 1464.48,2616.43 1472.35,2608.56 v1(1527.44,2608.56) 1598.27,2608.56 1645.49,2561.34 v1(1771.41,2561.34) ; v1(1385.78,2325.24) 1404.12,2306.9 1839.64,2306.9 1881.59,2348.85 1881.59,2364.59 1873.72,2372.46 ; v1(1393.65,2112.75) 1367.5,2138.9 1367.5,2228.9 1415.5,2276.9 1959.21,2276.9 1971.21,2288.9 v1(1977.21,2288.9) ; v1(1425.13,1923.87) v1(1338.56,1923.87) v1(1338.56,1860.91) 1425.21,1860.91 v1(1511.7,1860.91) ; v1(1425.13,3364.08) v1(1480.22,3364.08) ; v1(1439.21,1388.9) 1495.96,1332.15 v1(1495.96,1294.27) v1@1495.96,1292.52 ; 1489.3,3088.81 1508.36,3069.75 1508.36,3030.54 1547.2,2991.7 SB6.2@1547.2,2954.37 1549.21,2952.36 1549.21,2918.9 1559.21,2908.9 v1(1769.21,2908.9) ; v1(1566.93,3366.14) 1482.29,3366.14 v1(1480.22,3364.08) ; v1(1574.66,263.3) v1(1684.84,263.3) ; v1(1574.66,3308.99) v1@1574.66,3301.12 ; v1(1628.21,1404.9) 1659.21,1373.9 v1(1659.21,1248.9) v1(1729.21,1248.9) ; v1(1653.36,1553.98) 1669.1,1553.98 v1(1676.97,1546.11) 1676.97,1538.24 1724.19,1538.24 1787.15,1475.28 ; v1(1771.41,2482.64) 1936.68,2482.64 v1(1999.64,2419.68) v1(2019.21,2396.9) ; v1(1779.21,3178.9) 1779.21,3301.12 ; v1(1787.15,1420.19) 1787.15,1475.28 ; v1(1787.15,1491.02) 1787.15,1475.28 ; SB18.1@1787.15,2053.73 1818.63,2053.73 1827.21,2045.15 1827.21,1982.9 1846.89,1963.22 1905.2,1963.22 1913.07,1971.09 v1(1913.07,1986.83) v1(1999.64,1986.83) 2007.51,1978.96 2007.51,1955.35 2094.08,1868.78 2094.08,1758.6 2157.04,1695.64 2157.04,1601.2 v1(2188.52,1569.72) ; v1@1788.44,440.83 v1(1790.55,442.94) ; v1(1791.98,645.51) 1822.09,645.51 1834.37,657.8 v1(1834.37,741.73) 1833.72,741.08 1801.66,741.08 v1(1801.01,740.43) 1800.38,741.05 1800.38,779.63 v1@1800.25,779.76 ; v1(1799.76,779.76) v1@1800.25,779.76 ; v1(1832.23,779.96) 1832.13,779.86 1800.35,779.86 v1@1800.25,779.76 ; v1(1842.24,2372.46) 1873.72,2372.46 ; v1@1852.64,442.94 v1(1853.55,443.85) ; v1(1919.21,758.9) v1(1919.21,658.9) v1(1919.21,562.36) 1920.94,483.66 v1(1976.03,428.57) 1992.13,412.47 1996.21,408.39 1996.21,264.62 1992.13,260.54 v1(1992.13,255.91) ; v1(1952.42,1931.74) 1966.55,1931.74 2062.6,1835.69 2062.6,1742.86 2125.56,1679.9 2125.56,1561.85 v1(2164.91,1522.5) ; v1(1976.03,2325.24) 1972,2329.27 1972,2335.67 1935.21,2372.46 1873.72,2372.46 ; v1(2038.99,3301.12) v1(1913.07,3301.12) 1779.21,3301.12 ; v1(2289.21,2728.9) v1@2549.21,2728.9 ; v1(2549.21,2718.9) v1@2549.21,2728.9 ; v1(2549.21,3628.9) v1(2549.21,3438.9) v1(2549.21,3238.9) v1(2549.21,2998.9) v1@2549.21,2728.9 ; v1(639.21,498.9) v1(559.21,498.9) 557.21,500.9 v1(557.21,585.9) v1(557.21,718.9) 648.21,718.9 ; 648.21,718.9 v1(699.21,718.9) ; v1(699.21,718.9) v1(699.21,898.9) ; v1(1480.22,3364.08) v1(1480.22,3316.86) 1495.96,3301.12 v1@1574.66,3301.12 ; v1@1574.66,3301.12 1779.21,3301.12
  Bottom w11.81: v1(1459.21,3118.9) 1489.3,3088.81
  Bottom w12: v1(1259.37,1042.43) 1259.37,1008.95 1255.59,1005.17 1255.59,974.84 1267.54,962.9 v1@1305.21,962.9 ; C61.2@1307.08,2798.92 C61.2@1311.21,2798.92 ; 1347.61,2733.3 1311.21,2769.7 C61.2@1311.21,2798.92 ; 1361.61,2820.48 1340.04,2798.92 C61.2@1311.21,2798.92 ; v1(1790.55,442.94) v1@1852.64,442.94
  Bottom w12.01: 197.4,3635.79 JP2.1@248,3687 ; 198,3738 JP2.1@248.8,3687.81 ; JP2.1@249.21,3687.4 JP2.1@248.8,3687.81 ; 298.6,3738.21 JP2.1@248.8,3687.81 ; 299.21,3636.4 248.41,3686.59 JP2.1@248,3687 ; 1237.81,28.17 CN5.0@1284.84,74.62 ; 1238.39,150.79 CN5.0@1284.84,103.76 ; CN5.0@1285,72 1331.45,24.97 ; CN5.0@1286,103 1331.29,146.68 ; 1566.55,28.17 CN5.0@1613.58,74.62 1660.03,27.58 ; 1567.13,146.68 1611.53,101.73 CN5.0@1613.58,99.64 ; CN5.0@1613.58,103.76 1660.62,150.21 ; 2297.79,3736.6 2348.41,3686.59 JP3.1@2349,3686 ; 2298.4,3634.79 JP3.1@2349,3686 ; JP3.1@2349.21,3687.4 2399.81,3738.61 ; 2400.21,3635.4 JP3.1@2349,3686 ; JP2.1@248,3687 JP2.1@248.8,3687.81
  Bottom w15: v1(1214.87,517.93) 1214.87,520.26 1209.73,525.4 1209.73,530.76 1209.99,531.02 1220.61,531.02 1334.99,645.4 v1(1334.99,786.72) 1369.41,821.14 1369.41,878.9 1306.71,941.6 v1(1306.71,961.4) v1@1305.21,962.9
  Bottom w15.75: v1(379.21,3178.9) 339.21,3138.9 v1(339.21,3018.9) v1(339.21,2918.9) 339.21,2828.9 369.21,2798.9 526.93,2798.9 566.93,2758.9 v1(566.93,2688.98)
  Bottom w19.68: v1(811.02,2759.84) 818.9,2751.97 874.02,2751.97 918.21,2751.97 918.21,2771.9 v1(927.21,2780.9) ; v1(1899.21,948.9) 1919.21,928.9 v1(1919.21,898.9)
  Bottom w20: v1(453.21,2024.9) 480.21,1997.9 480.21,1991.9 v1(627.21,1844.9) ; v1(732.57,1908.13) 744.38,1919.93 779.79,1919.93 ; SB19.1@779.79,1912.07 779.79,1919.93 ; v1(811.27,2120.62) 846.24,2120.62 854.11,2112.75 854.11,1919.93 ; SB10.1@874.02,2751.97 SB10.1@874.02,2755.91 ; v1(905.71,1538.24) 952.93,1585.46 952.93,1640.55 929.32,1664.16 929.32,1900.26 909.65,1919.93 854.11,1919.93 ; v1(1110.33,1097.52) 1212.59,1097.52 1230.39,1079.72 1230.39,1072.39 1259.37,1043.41 v1(1259.37,1042.43) ; v1(1393.65,2112.75) v1(1448.74,2112.75) 1703.94,2112.75 1747.8,2068.88 1783.19,2068.88 1786.72,2065.35 SB18.1@1787.15,2053.73 ; v1(1425.21,1862.9) 1425.21,1860.91 1425.21,1742.86 v1(1472.35,1742.86) 1503.83,1742.86 1551.05,1695.64 1551.05,1609.07 1606.14,1553.98 v1(1653.36,1553.98) ; v1@1495.96,1292.52 1495.96,1278.53 ; v1@1519.57,2679.26 1519.7,2679.39 v1(1732.06,2679.39) v1(1802.89,2679.39) v1(1881.59,2679.39) ; v1(1533.71,815.81) 1534.4,816.51 1534.4,819.07 1535.31,819.98 1535.31,869.29 1495.96,908.64 1495.96,955.86 1503.83,963.73 1511.7,971.6 1511.7,1238.9 1495.96,1254.64 1495.96,1278.53 ; v1(1535.31,1278.53) 1495.96,1278.53 ; v1(1590.21,2378.9) v1(1755.67,2378.9) ; 779.79,1919.93 854.11,1919.93
  other v1: 583.04,748.41 1016.75,831.3 1081.15,832.59
LED_STLINK: R3.1 R4.1 U2.30 | length 1421.8
  Top w6.5: R4.1@673.19,3346.97 R3.1@614.13,3346.97 v1(614.17,3311.02) ; v1(1305.21,3062.9) 1306.43,3064.12 1323.21,3064.12 1362.17,3025.16 U2.30@1403.57,3025.16 ; v1(614.17,3311.02) v1(614.17,3311.02)
  Bottom w6.5: v1(614.17,3311.02) 614.17,3282.93 582.68,3251.44 582.68,2931.59 630.26,2884.01 1035.9,2884.01 1055.24,2903.35 1112.01,2903.35 1273.68,3065.02 1305.21,3065.02 v1(1305.21,3062.9)
MCO: C61.1 R25.1 R68.2 SB13.1 U4.12 | length 863.3
  Top w6.5: v1(1269.21,2678.9) 1269.21,2573.9 1250.21,2554.9 1250.21,2333.9 1264.21,2319.9 R25.1@1285.21,2319.9 1285.21,2300.9 1305.65,2280.46 U4.12@1305.65,2220.94
  Bottom w6.5: v1(1269.21,2678.9) 1273.52,2674.59 1306.21,2674.59 SB13.1@1318.88,2687.26 1305.21,2687.26 1305.21,2726.9 1263.21,2768.9 1263.21,2846.92 1275.21,2858.92 C61.1@1307.08,2858.92 R68.2@1307.08,2924.84
MICVDD: C47.2 C53.2 L5.2 U7.19 | length 261.4
  Top w6.5: U7.19@1125,776.76 1152.07,776.76 1167.91,760.92 L5.2@1167.91,680.03 1167.91,618.37 C53.2@1181.16,605.12 1184.79,608.75 1221.46,608.75 C47.2@1227.68,614.96
NetB1_1: B1.1 B1.2 C38.1 R35.2 R39.2 | length 573.8
  Top w6.5: R35.2@813.21,1472.9 813.21,1442.9 831.21,1424.9 831.21,1406.9 C38.1@833.21,1406.9 836.67,1407.76 841.81,1412.9 R39.2@897.21,1412.9
  Top w15.75: B1.1@649.62,1339.09 897.21,1339.09 ; R39.2@897.21,1412.9 897.21,1339.09 ; B1.2@1007.89,1339.09 897.21,1339.09
NetB2_3: B2.3 B2.4 C37.2 R37.1 SB1.2 | length 638.7
  Top w6.5: R37.1@1759.93,1459.54 C37.2@1810.76,1459.54 ; SB1.2@1818.62,1546.11 1814.37,1541.86 C37.2@1814.37,1459.54 ; C37.2@1810.76,1459.54 C37.2@1814.37,1459.54 ; C37.2@1810.76,1459.54 1812.57,1457.73 1810.76,1455.93 1810.76,1451.67 1813.54,1457.73 C37.2@1814.37,1459.54
  Top w15.75: B2.4@1590.53,1339.88 1759.93,1339.88 ; R37.1@1759.93,1459.54 1759.93,1339.88 ; B2.3@1948.8,1339.88 1759.93,1339.88
NetC3_1: C3.1 C4.2 D3.1 U1.5 | length 259.3
  Top w11.81: U1.5@1950.75,3364.21 1950.75,3378.9 2009.21,3378.9 C3.1@2029.21,3398.9
  Top w15.75: C3.1@2029.21,3398.9 C4.2@2101.64,3398.9
  Top w19.68: D3.1@2098.39,3317.36 2098.39,3328.07 2101.71,3331.4 2101.71,3383.91 2101.64,3398.9 C4.2@2101.71,3401.4
NetC5_2: C5.2 U1.4 | length 117.2
  Top w9.84: C5.2@1793.74,3327.6 1859.86,3327.6 1869.86,3337.6 1869.86,3367.23 1872.93,3367.23 U1.4@1875.95,3364.21
NetC13_2: C13.2 U3.4 | length 115.8
  Top w20: C13.2@455.2,2728.35 454.72,2727.87 454.72,2688.98 472.44,2671.26 U3.4@523.62,2671.26
NetC14_2: C14.2 R24.1 X2.1 | length 302.3
  Top w6.5: C14.2@1095.21,2636.9 1093.53,2635.22 1093.53,2625.89 1108.66,2610.76 X2.1@1108.66,2507.87 1178.31,2438.22 1201.21,2415.32 R24.1@1201.21,2379.9
NetC15_2: C15.2 R25.2 X2.2 | length 277.7
  Top w6.5: R25.2@1285.21,2379.9 1285.21,2427.32 1300.79,2442.9 X2.2@1300.79,2507.87 1300.79,2576.9 1335.21,2611.32 C15.2@1335.21,2636.9
NetC16_1: C16.1 R22.2 X3.4 | length 256.8
  Top w6.5: R22.2@1533.94,2460.63 1533.94,2465.04 1576,2507.11 1576,2539.78 1599.21,2562.99 X3.4@1631.89,2562.99 1631.89,2657.01 C16.1@1631.42,2657.48
NetC21_2: C21.2 C23.1 R23.1 U4.21 | length 543.2
  Top w6.5: 963.9,2320.19 974.31,2309.78 1106.1,2309.78 1128.48,2287.4 U4.21@1128.48,2220.94
  Top w20: C21.2@858.27,2487.87 858.27,2459.25 ; R23.1@858.49,2418.2 858.27,2418.42 858.27,2459.25 ; 963.9,2320.19 937.01,2347.08 C23.1@937.01,2427.38 937.01,2452.76 858.49,2452.76 858.49,2459.03 858.27,2459.25
NetC22_1: C22.1 C25.2 L1.2 R23.2 U4.22 | length 647.4
  Top w6.5: 937.01,2295.28 1091.54,2295.28 1108.8,2278.02 U4.22@1108.8,2220.94
  Top w20: C22.1@693.22,2366.46 C22.1@693.22,2378.55 ; L1.2@765.53,2358.2 L1.2@779.79,2358.2 ; R23.2@858.49,2358.2 859.97,2356.72 875.57,2356.72 937.01,2295.28
  Top w30: C25.2@614.52,2360.33 685.35,2360.33 ; C22.1@693.22,2366.46 685.35,2366.46 685.35,2360.33 ; L1.2@765.53,2358.2 L1.2@763.4,2360.33 ; L1.2@779.79,2358.2 777.66,2360.33 L1.2@763.4,2360.33 ; R23.2@858.49,2358.2 857.87,2358.35 855.4,2360.82 762.9,2360.82 L1.2@763.4,2360.33 ; 685.35,2360.33 L1.2@763.4,2360.33
NetC27_1: C27.1 R21.2 X3.1 | length 366
  Top w6.5: R21.2@1533.94,2531.5 1533.94,2561.34 1549.68,2577.08 v1(1566.79,2577.08) ; v1(1582.53,2466.9) 1631.89,2466.9 X3.1@1631.89,2437.01 1647.17,2421.73 C27.1@1647.17,2342.52
  Bottom w6.5: v1(1566.79,2577.08) 1579.21,2564.66 1579.21,2470.22 v1(1582.53,2466.9)
NetC28_1: C28.1 R26.2 U4.6 | length 197.8
  Top w6.5: U4.6@1423.76,2220.94 1423.76,2257.4 1486.75,2320.39 R26.2@1488.19,2320.39 C28.1@1559.06,2320.39
NetC33_1: C33.1 U4.49 | length 237.8
  Top w10: C33.1@820.92,1569.72 803.29,1569.55 809.19,1575.45 821.23,1575.45 937.19,1691.41 U4.49@972.97,1691.41
NetC36_1: C36.1 U4.73 | length 169.8
  Top w6.5: U4.73@1482.81,1594.96 1482.81,1506.76 1540.21,1449.36 C36.1@1540.21,1448.9
NetC38_2: C38.2 R38.1 | length 56
  Top w6.5: R38.1@737.21,1406.9 C38.2@793.21,1406.9
NetC44_1: C44.1 R47.1 | length 61.8
  Top w6.5: R47.1@1264.12,900.77 1319.94,900.77 1321.66,902.49 C44.1@1325.2,902.6
NetC44_2: C44.2 R44.1 R48.1 | length 136.9
  Top w6.5: R44.1@1405.2,962.6 1390.41,962.6 1385.2,957.38 C44.2@1385.2,902.6 R48.1@1445.2,902.6
NetC51_1: C51.1 R53.1 | length 202.3
  Top w6.5: R53.1@1295.59,841.18 1322.8,841.18 1359.21,804.77 1359.21,716.61 1351.95,709.35 1349.45,709.35 1335.2,695.1 C51.1@1335.2,692.6
NetC51_2: C51.2 C52.1 R49.2 R52.1 R54.1 | length 310.6
  Top w6.5: R54.1@1335.2,612.6 1395.83,673.23 C51.2@1395.83,692.6 ; R49.2@1395.13,822.07 1395.13,760.04 1394.88,759.79 R52.1@1391.71,758.9 1391.71,692.6 C51.2@1395.2,692.6 C51.2@1395.83,692.6 ; C52.1@1465.2,692.6 C51.2@1395.83,692.6
NetC54_1: C54.1 U7.8 | length 102
  Top w6.5: C54.1@937.68,671.3 940.05,673.67 940.05,734.44 950.88,745.26 U7.8@973.42,745.26
NetC54_2: C54.2 U7.10 | length 60.4
  Top w6.5: C54.2@992.8,671.3 1009.84,688.34 U7.10@1009.84,724.59
NetC55_2: C55.2 U7.11 | length 132.3
  Top w6.5: C55.2@964.89,631.87 989.5,631.87 1025.59,667.97 U7.11@1025.59,724.59
NetC56_2: C56.2 U7.12 | length 106.7
  Top w6.5: C56.2@1024.25,625.01 1026.06,626.82 1026.06,643.55 1041.34,658.82 U7.12@1041.34,724.59
NetC57_2: C57.2 U7.21 | length 432.4
  Top w6.5: U7.21@1125.25,808 1197.15,808 1214.87,790.28 1214.87,680.03 1289.21,605.69 1289.21,583.15 1310.34,562.03 C57.2@1377.95,562.03
NetC59_1: C59.1 CN4.2 L7.2 | length 899.7
  Top w6.5: CN4.2@659.84,155.91 583.04,232.71 583.04,410.83 610.93,438.72 762.8,438.72 832.62,368.9 1004.31,368.9 1032.59,397.18 1032.59,413.55 C59.1@1033.57,413.55 ; C59.1@1033.18,413.16 C59.1@1033.57,413.55 ; C59.1@1037.98,413.55 C59.1@1033.57,413.55 ; L7.2@1038.08,492.7 1047.62,483.15 1047.62,427.6 C59.1@1033.57,413.55
NetC62_1: C62.1 CN4.3 L6.2 | length 635.9
  Top w6.5: CN4.3@676.53,372.44 CN4.3@659.84,372.44 717.83,314.45 1043.2,314.45 1120.28,391.53 C62.1@1120.28,414.14 1119.57,414.85 1119.57,480.86 L6.2@1110.24,490.2
NetC63_1: C63.1 R71.2 | length 49.7
  Top w6.5: C63.1@1149.21,513.83 1149.21,485.44 R71.2@1164.25,470.4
